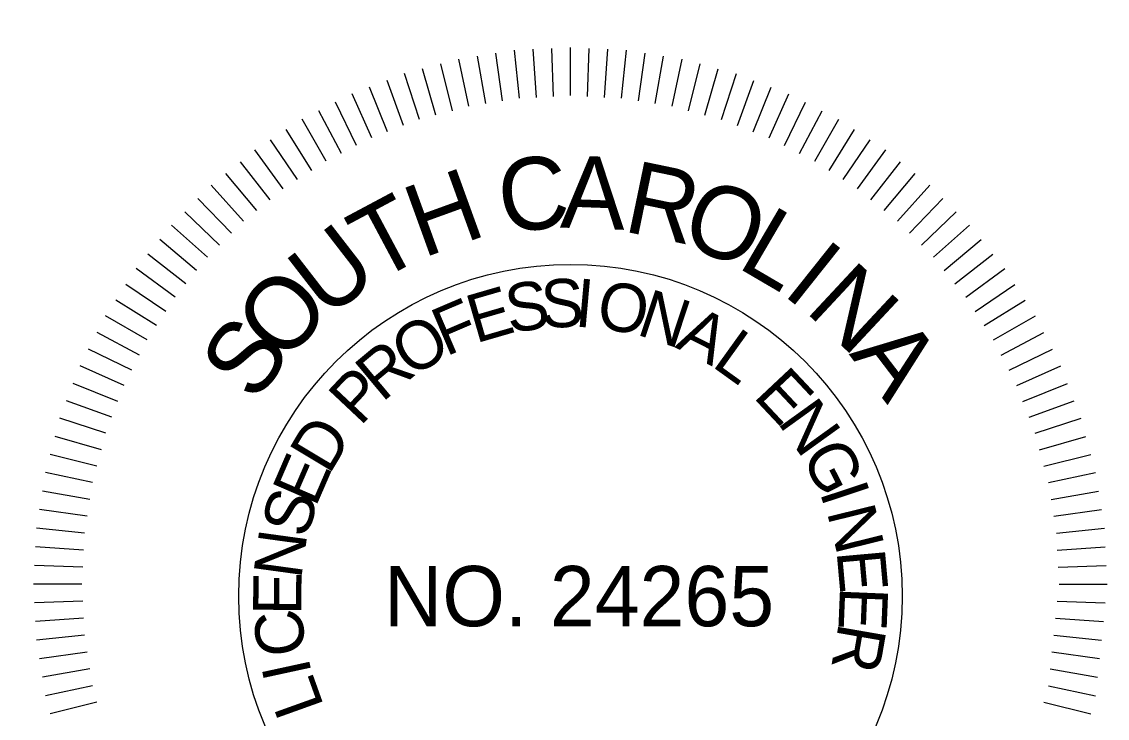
# Model space of a CAD drawing. Extents: x 1964849 to 1967422, y 1116563 to 1122210.
# Drawn here: x 1967328.2 to 1967408.3, y 1118279.6 to 1118331 of the extents above; entities that cross this region are included whole.
import ezdxf

# ---------------------------------------------------------------- set-up
doc = ezdxf.new("R2010")
doc.units = 0
doc.layers.add('RD_SHT_MatchLine', color=7, linetype='Continuous')
doc.layers.add('RD_TX_PEShield', color=7, linetype='Continuous')

msp = doc.modelspace()

# ---------------------------------------------------------------- linework, layer by layer
at = {"layer": 'RD_TX_PEShield'}
for p, q in [((1967363.692, 1118325.155), (1967363.198, 1118328.676)), ((1967363.692, 1118325.155), (1967363.198, 1118328.676)), ((1967364.935, 1118325.352), (1967364.563, 1118328.892)), ((1967364.935, 1118325.352), (1967364.563, 1118328.892)), ((1967366.191, 1118325.418), (1967365.943, 1118328.965)), ((1967366.191, 1118325.418), (1967365.943, 1118328.965)), ((1967367.446, 1118325.484), (1967367.322, 1118329.037)), ((1967367.446, 1118325.484), (1967367.322, 1118329.037)), ((1967368.703, 1118325.549), (1967368.703, 1118329.109)), ((1967368.703, 1118325.549), (1967368.703, 1118329.109)), ((1967369.959, 1118325.484), (1967370.083, 1118329.037)), ((1967369.959, 1118325.484), (1967370.083, 1118329.037)), ((1967371.214, 1118325.418), (1967371.462, 1118328.965)), ((1967371.214, 1118325.418), (1967371.462, 1118328.965)), ((1967372.471, 1118325.352), (1967372.843, 1118328.892)), ((1967372.471, 1118325.352), (1967372.843, 1118328.892)), ((1967373.713, 1118325.155), (1967374.208, 1118328.676)), ((1967373.713, 1118325.155), (1967374.208, 1118328.676)), ((1967359.993, 1118324.436), (1967359.133, 1118327.886)), ((1967359.993, 1118324.436), (1967359.133, 1118327.886)), ((1967361.209, 1118324.762), (1967360.468, 1118328.244)), ((1967361.209, 1118324.762), (1967360.468, 1118328.244)), ((1967362.451, 1118324.959), (1967361.834, 1118328.46)), ((1967362.451, 1118324.959), (1967361.834, 1118328.46)), ((1967374.954, 1118324.959), (1967375.572, 1118328.46)), ((1967374.954, 1118324.959), (1967375.572, 1118328.46)), ((1967376.197, 1118324.762), (1967376.937, 1118328.244)), ((1967376.197, 1118324.762), (1967376.937, 1118328.244)), ((1967376.197, 1118324.762), (1967376.937, 1118328.244)), ((1967377.412, 1118324.436), (1967378.272, 1118327.886)), ((1967377.412, 1118324.436), (1967378.272, 1118327.886)), ((1967377.412, 1118324.436), (1967378.272, 1118327.886)), ((1967357.564, 1118323.785), (1967356.464, 1118327.171)), ((1967357.564, 1118323.785), (1967356.464, 1118327.171)), ((1967358.78, 1118324.111), (1967357.799, 1118327.529)), ((1967358.78, 1118324.111), (1967357.799, 1118327.529)), ((1967378.626, 1118324.111), (1967379.606, 1118327.529)), ((1967378.626, 1118324.111), (1967379.606, 1118327.529)), ((1967378.626, 1118324.111), (1967379.606, 1118327.529)), ((1967379.841, 1118323.785), (1967380.941, 1118327.171)), ((1967379.841, 1118323.785), (1967380.941, 1118327.171)), ((1967379.841, 1118323.785), (1967380.941, 1118327.171)), ((1967355.217, 1118322.884), (1967353.885, 1118326.181)), ((1967355.217, 1118322.884), (1967353.885, 1118326.181)), ((1967356.39, 1118323.334), (1967355.174, 1118326.676)), ((1967356.39, 1118323.334), (1967355.174, 1118326.676)), ((1967381.016, 1118323.334), (1967382.232, 1118326.676)), ((1967381.016, 1118323.334), (1967382.232, 1118326.676)), ((1967381.016, 1118323.334), (1967382.232, 1118326.676)), ((1967382.189, 1118322.884), (1967383.521, 1118326.181)), ((1967382.189, 1118322.884), (1967383.521, 1118326.181)), ((1967382.189, 1118322.884), (1967383.521, 1118326.181)), ((1967354.042, 1118322.433), (1967352.594, 1118325.685)), ((1967354.042, 1118322.433), (1967352.594, 1118325.685)), ((1967383.364, 1118322.433), (1967384.812, 1118325.685)), ((1967383.364, 1118322.433), (1967384.812, 1118325.685)), ((1967383.364, 1118322.433), (1967384.812, 1118325.685)), ((1967352.921, 1118321.862), (1967351.362, 1118325.058)), ((1967352.921, 1118321.862), (1967351.362, 1118325.058)), ((1967384.485, 1118321.862), (1967386.043, 1118325.058)), ((1967384.485, 1118321.862), (1967386.043, 1118325.058)), ((1967384.485, 1118321.862), (1967386.043, 1118325.058)), ((1967350.68, 1118320.72), (1967348.9, 1118323.803)), ((1967350.68, 1118320.72), (1967348.9, 1118323.803)), ((1967351.801, 1118321.292), (1967350.132, 1118324.431)), ((1967351.801, 1118321.292), (1967350.132, 1118324.431)), ((1967385.604, 1118321.292), (1967387.274, 1118324.431)), ((1967385.604, 1118321.292), (1967387.274, 1118324.431)), ((1967385.604, 1118321.292), (1967387.274, 1118324.431)), ((1967386.725, 1118320.72), (1967388.505, 1118323.803)), ((1967386.725, 1118320.72), (1967388.505, 1118323.803)), ((1967386.725, 1118320.72), (1967388.505, 1118323.803)), ((1967349.625, 1118320.035), (1967347.741, 1118323.05)), ((1967349.625, 1118320.035), (1967347.741, 1118323.05)), ((1967387.78, 1118320.035), (1967389.665, 1118323.05)), ((1967387.78, 1118320.035), (1967389.665, 1118323.05)), ((1967387.78, 1118320.035), (1967389.665, 1118323.05)), ((1967348.571, 1118319.351), (1967346.583, 1118322.298)), ((1967348.571, 1118319.351), (1967346.583, 1118322.298)), ((1967388.834, 1118319.351), (1967390.823, 1118322.298)), ((1967388.834, 1118319.351), (1967390.823, 1118322.298)), ((1967388.834, 1118319.351), (1967390.823, 1118322.298)), ((1967347.516, 1118318.665), (1967345.424, 1118321.546)), ((1967347.516, 1118318.665), (1967345.424, 1118321.546)), ((1967389.89, 1118318.665), (1967391.982, 1118321.546)), ((1967389.89, 1118318.665), (1967391.982, 1118321.546)), ((1967389.89, 1118318.665), (1967391.982, 1118321.546)), ((1967346.538, 1118317.874), (1967344.349, 1118320.676)), ((1967346.538, 1118317.874), (1967344.349, 1118320.676)), ((1967390.867, 1118317.874), (1967393.056, 1118320.676)), ((1967390.867, 1118317.874), (1967393.056, 1118320.676)), ((1967390.867, 1118317.874), (1967393.056, 1118320.676)), ((1967345.562, 1118317.083), (1967343.276, 1118319.807)), ((1967345.562, 1118317.083), (1967343.276, 1118319.807)), ((1967391.844, 1118317.083), (1967394.129, 1118319.807)), ((1967391.844, 1118317.083), (1967394.129, 1118319.807)), ((1967391.844, 1118317.083), (1967394.129, 1118319.807)), ((1967344.584, 1118316.291), (1967342.202, 1118318.937)), ((1967344.584, 1118316.291), (1967342.202, 1118318.937)), ((1967392.822, 1118316.291), (1967395.204, 1118318.937)), ((1967392.822, 1118316.291), (1967395.204, 1118318.937)), ((1967392.822, 1118316.291), (1967395.204, 1118318.937)), ((1967343.694, 1118315.401), (1967341.224, 1118317.959)), ((1967343.694, 1118315.401), (1967341.224, 1118317.959)), ((1967393.711, 1118315.401), (1967396.181, 1118317.959)), ((1967393.711, 1118315.401), (1967396.181, 1118317.959)), ((1967393.711, 1118315.401), (1967396.181, 1118317.959)), ((1967342.806, 1118314.513), (1967340.248, 1118316.983)), ((1967342.806, 1118314.513), (1967340.248, 1118316.983)), ((1967394.6, 1118314.513), (1967397.158, 1118316.983)), ((1967394.6, 1118314.513), (1967397.158, 1118316.983)), ((1967394.6, 1118314.513), (1967397.158, 1118316.983)), ((1967341.916, 1118313.623), (1967339.271, 1118316.005)), ((1967341.916, 1118313.623), (1967339.271, 1118316.005)), ((1967395.489, 1118313.623), (1967398.135, 1118316.005)), ((1967395.489, 1118313.623), (1967398.135, 1118316.005)), ((1967395.489, 1118313.623), (1967398.135, 1118316.005)), ((1967341.124, 1118312.645), (1967338.401, 1118314.931)), ((1967341.124, 1118312.645), (1967338.401, 1118314.931)), ((1967396.281, 1118312.645), (1967399.005, 1118314.931)), ((1967396.281, 1118312.645), (1967399.005, 1118314.931)), ((1967396.281, 1118312.645), (1967399.005, 1118314.931)), ((1967340.334, 1118311.669), (1967337.532, 1118313.858)), ((1967340.334, 1118311.669), (1967337.532, 1118313.858)), ((1967397.072, 1118311.669), (1967399.874, 1118313.858)), ((1967397.072, 1118311.669), (1967399.874, 1118313.858)), ((1967397.072, 1118311.669), (1967399.874, 1118313.858)), ((1967339.542, 1118310.691), (1967336.662, 1118312.784)), ((1967339.542, 1118310.691), (1967336.662, 1118312.784)), ((1967397.864, 1118310.691), (1967400.744, 1118312.784)), ((1967397.864, 1118310.691), (1967400.744, 1118312.784)), ((1967397.864, 1118310.691), (1967400.744, 1118312.784)), ((1967338.857, 1118309.636), (1967335.909, 1118311.624)), ((1967338.857, 1118309.636), (1967335.909, 1118311.624)), ((1967398.549, 1118309.636), (1967401.497, 1118311.624)), ((1967398.549, 1118309.636), (1967401.497, 1118311.624)), ((1967398.549, 1118309.636), (1967401.497, 1118311.624)), ((1967338.172, 1118308.582), (1967335.157, 1118310.466)), ((1967338.172, 1118308.582), (1967335.157, 1118310.466)), ((1967399.233, 1118308.582), (1967402.249, 1118310.466)), ((1967399.233, 1118308.582), (1967402.249, 1118310.466)), ((1967399.233, 1118308.582), (1967402.249, 1118310.466)), ((1967337.487, 1118307.527), (1967334.404, 1118309.307)), ((1967337.487, 1118307.527), (1967334.404, 1118309.307)), ((1967399.919, 1118307.527), (1967403.002, 1118309.307)), ((1967399.919, 1118307.527), (1967403.002, 1118309.307)), ((1967399.919, 1118307.527), (1967403.002, 1118309.307)), ((1967336.916, 1118306.406), (1967333.776, 1118308.075)), ((1967336.916, 1118306.406), (1967333.776, 1118308.075)), ((1967400.49, 1118306.406), (1967403.629, 1118308.075)), ((1967400.49, 1118306.406), (1967403.629, 1118308.075)), ((1967400.49, 1118306.406), (1967403.629, 1118308.075)), ((1967336.345, 1118305.286), (1967333.149, 1118306.845)), ((1967336.345, 1118305.286), (1967333.149, 1118306.845)), ((1967401.06, 1118305.286), (1967404.256, 1118306.845)), ((1967401.06, 1118305.286), (1967404.256, 1118306.845)), ((1967401.06, 1118305.286), (1967404.256, 1118306.845)), ((1967335.774, 1118304.165), (1967332.522, 1118305.613)), ((1967335.774, 1118304.165), (1967332.522, 1118305.613)), ((1967401.632, 1118304.165), (1967404.884, 1118305.613)), ((1967401.632, 1118304.165), (1967404.884, 1118305.613)), ((1967401.632, 1118304.165), (1967404.884, 1118305.613)), ((1967335.323, 1118302.991), (1967332.026, 1118304.323)), ((1967335.323, 1118302.991), (1967332.026, 1118304.323)), ((1967402.082, 1118302.991), (1967405.379, 1118304.323)), ((1967402.082, 1118302.991), (1967405.379, 1118304.323)), ((1967402.082, 1118302.991), (1967405.379, 1118304.323)), ((1967334.873, 1118301.818), (1967331.532, 1118303.034)), ((1967334.873, 1118301.818), (1967331.532, 1118303.034)), ((1967402.533, 1118301.818), (1967405.874, 1118303.034)), ((1967402.533, 1118301.818), (1967405.874, 1118303.034)), ((1967402.533, 1118301.818), (1967405.874, 1118303.034)), ((1967334.422, 1118300.643), (1967331.036, 1118301.743)), ((1967334.422, 1118300.643), (1967331.036, 1118301.743)), ((1967402.984, 1118300.643), (1967406.369, 1118301.743)), ((1967402.984, 1118300.643), (1967406.369, 1118301.743)), ((1967402.984, 1118300.643), (1967406.369, 1118301.743)), ((1967334.096, 1118299.428), (1967330.678, 1118300.408)), ((1967334.096, 1118299.428), (1967330.678, 1118300.408)), ((1967403.309, 1118299.428), (1967406.727, 1118300.408)), ((1967403.309, 1118299.428), (1967406.727, 1118300.408)), ((1967403.309, 1118299.428), (1967406.727, 1118300.408)), ((1967333.771, 1118298.214), (1967330.321, 1118299.074)), ((1967333.771, 1118298.214), (1967330.321, 1118299.074)), ((1967403.634, 1118298.214), (1967407.085, 1118299.074)), ((1967403.634, 1118298.214), (1967407.085, 1118299.074)), ((1967403.634, 1118298.214), (1967407.085, 1118299.074)), ((1967333.445, 1118296.999), (1967329.963, 1118297.739)), ((1967333.445, 1118296.999), (1967329.963, 1118297.739)), ((1967403.96, 1118296.999), (1967407.442, 1118297.739)), ((1967403.96, 1118296.999), (1967407.442, 1118297.739)), ((1967403.96, 1118296.999), (1967407.442, 1118297.739)), ((1967333.249, 1118295.756), (1967329.747, 1118296.373)), ((1967333.249, 1118295.756), (1967329.747, 1118296.373)), ((1967404.157, 1118295.756), (1967407.659, 1118296.373)), ((1967404.157, 1118295.756), (1967407.659, 1118296.373)), ((1967404.157, 1118295.756), (1967407.659, 1118296.373)), ((1967333.052, 1118294.515), (1967329.531, 1118295.01)), ((1967333.052, 1118294.515), (1967329.531, 1118295.01)), ((1967404.354, 1118294.515), (1967407.875, 1118295.01)), ((1967404.354, 1118294.515), (1967407.875, 1118295.01)), ((1967404.354, 1118294.515), (1967407.875, 1118295.01)), ((1967332.855, 1118293.272), (1967329.315, 1118293.644)), ((1967332.855, 1118293.272), (1967329.315, 1118293.644)), ((1967404.55, 1118293.272), (1967408.091, 1118293.644)), ((1967404.55, 1118293.272), (1967408.091, 1118293.644)), ((1967404.55, 1118293.272), (1967408.091, 1118293.644)), ((1967332.789, 1118292.016), (1967329.242, 1118292.264)), ((1967332.789, 1118292.016), (1967329.242, 1118292.264)), ((1967404.616, 1118292.016), (1967408.163, 1118292.264)), ((1967404.616, 1118292.016), (1967408.163, 1118292.264)), ((1967404.616, 1118292.016), (1967408.163, 1118292.264)), ((1967332.724, 1118290.761), (1967329.17, 1118290.885)), ((1967332.724, 1118290.761), (1967329.17, 1118290.885)), ((1967404.682, 1118290.761), (1967408.235, 1118290.885)), ((1967404.682, 1118290.761), (1967408.235, 1118290.885)), ((1967404.682, 1118290.761), (1967408.235, 1118290.885)), ((1967332.658, 1118289.504), (1967329.098, 1118289.504)), ((1967332.658, 1118289.504), (1967329.098, 1118289.504)), ((1967404.748, 1118289.504), (1967408.308, 1118289.504)), ((1967404.748, 1118289.504), (1967408.308, 1118289.504)), ((1967404.748, 1118289.504), (1967408.308, 1118289.504)), ((1967332.724, 1118288.248), (1967329.17, 1118288.124)), ((1967332.724, 1118288.248), (1967329.17, 1118288.124)), ((1967404.616, 1118288.25), (1967408.163, 1118288.126)), ((1967404.616, 1118288.25), (1967408.163, 1118288.126)), ((1967332.789, 1118286.993), (1967329.242, 1118286.745)), ((1967332.789, 1118286.993), (1967329.242, 1118286.745)), ((1967404.485, 1118287.002), (1967408.019, 1118286.755)), ((1967404.485, 1118287.002), (1967408.019, 1118286.755)), ((1967332.855, 1118285.737), (1967329.315, 1118285.365)), ((1967332.855, 1118285.737), (1967329.315, 1118285.365)), ((1967404.354, 1118285.757), (1967407.875, 1118285.387)), ((1967404.354, 1118285.757), (1967407.875, 1118285.387)), ((1967333.052, 1118284.494), (1967329.531, 1118283.999)), ((1967333.052, 1118284.494), (1967329.531, 1118283.999)), ((1967404.223, 1118284.512), (1967407.731, 1118284.019)), ((1967404.223, 1118284.512), (1967407.731, 1118284.019)), ((1967333.249, 1118283.253), (1967329.747, 1118282.635)), ((1967333.249, 1118283.253), (1967329.747, 1118282.635)), ((1967404.092, 1118283.264), (1967407.587, 1118282.648)), ((1967404.092, 1118283.264), (1967407.587, 1118282.648)), ((1967333.445, 1118282.01), (1967329.963, 1118281.27)), ((1967333.445, 1118282.01), (1967329.963, 1118281.27)), ((1967403.96, 1118282.01), (1967407.442, 1118281.27)), ((1967403.96, 1118282.01), (1967407.442, 1118281.27)), ((1967333.771, 1118280.795), (1967330.321, 1118279.935)), ((1967333.771, 1118280.795), (1967330.321, 1118279.935)), ((1967403.634, 1118280.795), (1967407.085, 1118279.935)), ((1967403.634, 1118280.795), (1967407.085, 1118279.935))]:
    msp.add_line(p, q, dxfattribs=at)
msp.add_circle((1967368.703, 1118288.626), 24.475, dxfattribs=at)

# ---------------------------------------------------------------- texts
at = {"layer": 'RD_SHT_MatchLine'}
msp.add_text('Match Line Sta. 70+00.00 (See Sheet No. 8)', height=8, rotation=77.47237, dxfattribs=at).set_placement((1967305.004, 1118313.158))
at = {"layer": 'RD_TX_PEShield'}
for s, height, rotation, p in [('C', 5.34, 6.88322, (1967363.697, 1118315.364)), ('A', 5.34, 357.94482, (1967367.912, 1118315.817)), ('R', 5.34, 348.26699, (1967372.494, 1118315.563)), ('H', 5.34, 19.91024, (1967357.799, 1118313.548)), ('O', 5.34, 339.32858, (1967376.634, 1118314.647)), ('T', 5.34, 28.09472, (1967354.362, 1118311.742)), ('L', 5.34, 329.65075, (1967380.895, 1118312.943)), ('U', 5.34, 37.77255, (1967350.68, 1118309.002)), ('I', 5.34, 321.46627, (1967384.233, 1118310.96)), ('N', 5.34, 317.00069, (1967385.924, 1118309.683)), ('O', 5.34, 47.45038, (1967347.512, 1118305.682)), ('S', 3.56, 8.69092, (1967364.191, 1118308.014)), ('S', 3.56, 1.78995, (1967366.553, 1118308.416)), ('I', 3.56, 354.88899, (1967368.946, 1118308.531)), ('O', 3.56, 350.40454, (1967370.502, 1118308.451)), ('E', 3.56, 16.18428, (1967361.701, 1118307.26)), ('N', 3.56, 341.70291, (1967373.48, 1118307.951)), ('F', 3.56, 23.08525, (1967359.513, 1118306.284)), ('A', 3.56, 333.00129, (1967376.349, 1118307.005)), ('S', 5.34, 54.90268, (1967345.478, 1118302.789)), ('O', 3.56, 31.78688, (1967356.947, 1118304.69)), ('L', 3.56, 324.29966, (1967379.041, 1118305.637)), ('A', 5.34, 307.32286, (1967389.219, 1118306.488)), ('R', 3.56, 39.89024, (1967354.8, 1118302.873)), ('P', 3.56, 46.7912, (1967353.189, 1118301.099)), ('E', 3.56, 313.22511, (1967382.116, 1118303.334)), ('N', 3.56, 305.73175, (1967383.92, 1118301.459)), ('D', 3.56, 59.07401, (1967350.891, 1118297.513)), ('G', 3.56, 297.03012, (1967385.686, 1118299.01)), ('E', 3.56, 66.56738, (1967349.884, 1118295.115)), ('I', 3.56, 288.3285, (1967387.062, 1118296.321)), ('S', 3.56, 73.46834, (1967349.241, 1118292.806)), ('N', 3.56, 283.84405, (1967387.607, 1118294.862)), ('N', 3.56, 82.16997, (1967348.832, 1118289.814)), ('E', 3.56, 275.14243, (1967388.333, 1118291.93)), ('E', 3.56, 89.66334, (1967348.847, 1118287.212)), ('E', 3.56, 267.64906, (1967388.596, 1118289.342)), ('C', 3.56, 97.7667, (1967349.245, 1118284.428)), ('R', 3.56, 260.15569, (1967388.519, 1118286.741)), ('I', 3.56, 102.25114, (1967349.632, 1118282.919)), ('L', 3.56, 109.74451, (1967350.54, 1118280.481))]:
    msp.add_text(s, height=height, rotation=rotation, dxfattribs=at).set_placement(p)
msp.add_text('NO. 24265', height=4.4501, dxfattribs=at).set_placement((1967354.949, 1118286.401))

doc.saveas('drawing.dxf')
